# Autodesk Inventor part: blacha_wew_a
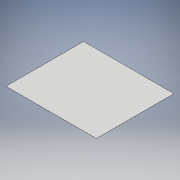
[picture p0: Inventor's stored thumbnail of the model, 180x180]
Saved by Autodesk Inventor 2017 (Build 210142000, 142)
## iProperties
Created: 2020-09
Part Number: blacha_wew_a
Material: Generic
Document SubType Name: Modeling
Designer: WindowsX
Density: 1 g/cm^3
Appearance: Default
Author: WindowsX
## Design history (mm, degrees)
sketch "Szkic1"
  geometry: L1 (0, 0)-(1130, 0); L2 (1130, 0)-(1130, 970); L3 (1130, 970)-(0, 970); L4 (0, 970)-(0, 0)
  constraints: 8 end point, 2 parallel, 1 horizontal, 1 perpendicular
  dimensions: "d0" = 1130 distance of L2.end L3.end; "d1" = 970 distance of L1.start L3.end
extrude "Wyciągnięcie proste1" new body sketch "Szkic1" distance "d2" = 1.5; taper "d3" = 0 deg
node "Bryła1"
